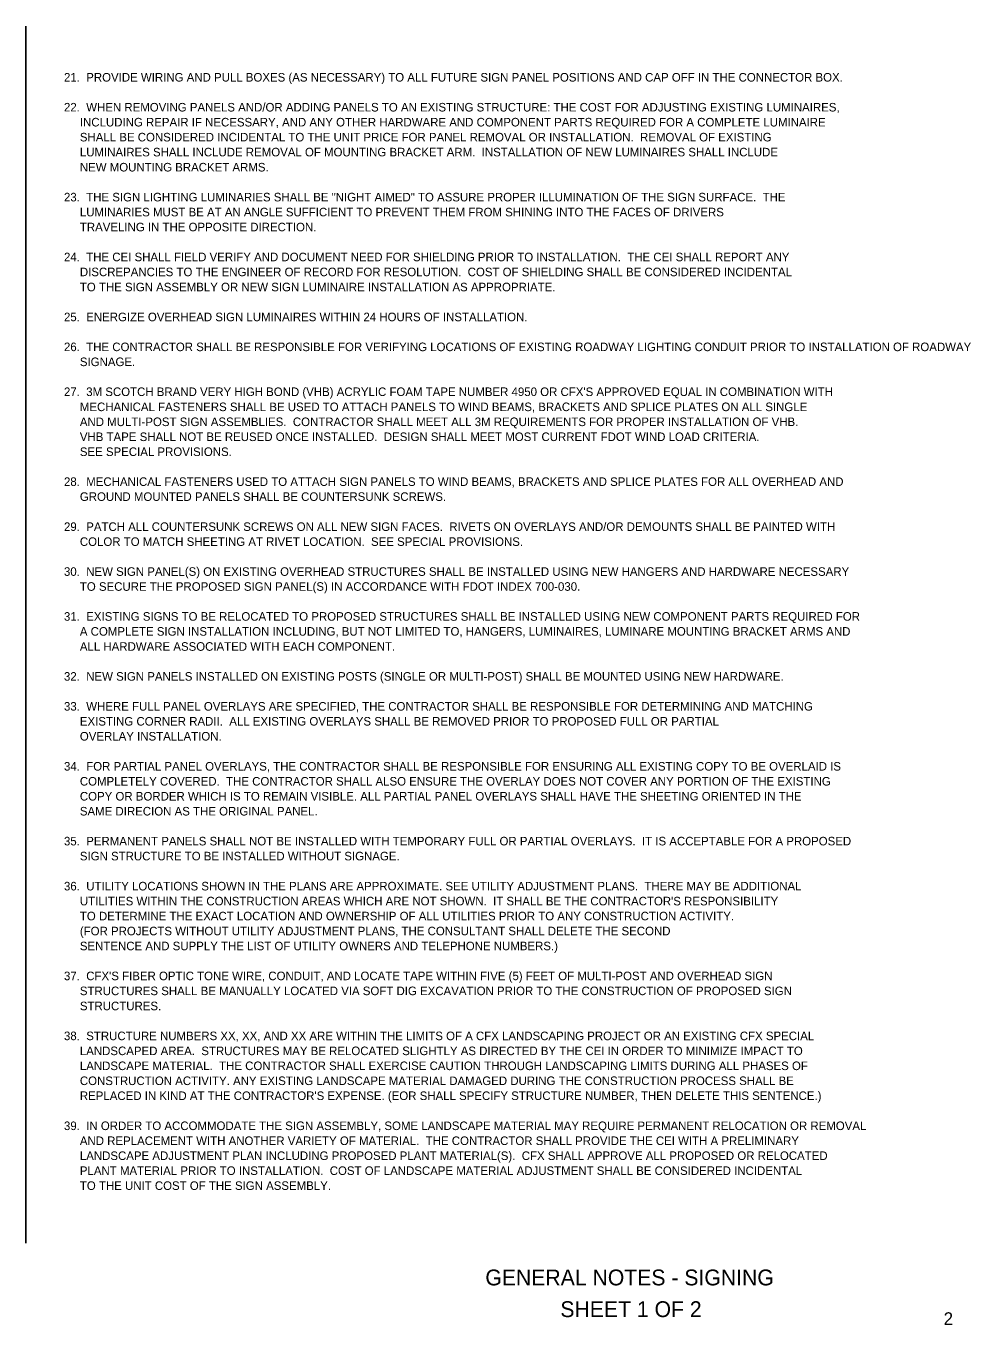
# Model space of a CAD drawing. Extents: x 2479946 to 2481516, y 3680184 to 3681234.
# Drawn here: x 2480771 to 2481516, y 3680210 to 3681234 of the extents above; entities that cross this region are included whole.
import ezdxf

# ---------------------------------------------------------------- set-up
doc = ezdxf.new("R2010")
doc.units = 0
for name, color, linetype in [('NonPlottingEle_dp', 7, 'Continuous'), ('TextLabel', 7, 'Continuous'), ('TextMisc', 7, 'Continuous'), ('TextShtNo', 7, 'Continuous')]:
    doc.layers.add(name, color=color, linetype=linetype)

msp = doc.modelspace()

# ---------------------------------------------------------------- linework, layer by layer
at = {"layer": 'NonPlottingEle_dp'}
msp.add_line((2480770.9, 3680274.2), (2480770.9, 3681234.2), dxfattribs=at)

# ---------------------------------------------------------------- texts
at = {"layer": 'TextLabel'}
for s, p in [('21.  PROVIDE WIRING AND PULL BOXES (AS NECESSARY) TO ALL FUTURE SIGN PANEL POSITIONS AND CAP OFF IN THE CONNECTOR BOX.', (2480800.9, 3681190.4)), ('22.  WHEN REMOVING PANELS AND/OR ADDING PANELS TO AN EXISTING STRUCTURE: THE COST FOR ADJUSTING EXISTING LUMINAIRES,', (2480800.9, 3681166.8)), ('     INCLUDING REPAIR IF NECESSARY, AND ANY OTHER HARDWARE AND COMPONENT PARTS REQUIRED FOR A COMPLETE LUMINAIRE', (2480800.9, 3681155)), ('     SHALL BE CONSIDERED INCIDENTAL TO THE UNIT PRICE FOR PANEL REMOVAL OR INSTALLATION.  REMOVAL OF EXISTING', (2480800.9, 3681143.2)), ('     LUMINAIRES SHALL INCLUDE REMOVAL OF MOUNTING BRACKET ARM.  INSTALLATION OF NEW LUMINAIRES SHALL INCLUDE', (2480800.9, 3681131.4)), ('     NEW MOUNTING BRACKET ARMS.', (2480800.9, 3681119.5)), ('23.  THE SIGN LIGHTING LUMINARIES SHALL BE "NIGHT AIMED" TO ASSURE PROPER ILLUMINATION OF THE SIGN SURFACE.  THE ', (2480800.9, 3681095.9)), ('     LUMINARIES MUST BE AT AN ANGLE SUFFICIENT TO PREVENT THEM FROM SHINING INTO THE FACES OF DRIVERS', (2480800.9, 3681084.1)), ('     TRAVELING IN THE OPPOSITE DIRECTION.', (2480800.9, 3681072.3)), ('24.  THE CEI SHALL FIELD VERIFY AND DOCUMENT NEED FOR SHIELDING PRIOR TO INSTALLATION.  THE CEI SHALL REPORT ANY', (2480800.9, 3681048.7)), ('     DISCREPANCIES TO THE ENGINEER OF RECORD FOR RESOLUTION.  COST OF SHIELDING SHALL BE CONSIDERED INCIDENTAL', (2480800.9, 3681036.9)), ('     TO THE SIGN ASSEMBLY OR NEW SIGN LUMINAIRE INSTALLATION AS APPROPRIATE.', (2480800.9, 3681025)), ('25.  ENERGIZE OVERHEAD SIGN LUMINAIRES WITHIN 24 HOURS OF INSTALLATION.', (2480800.9, 3681001.4)), ('26.  THE CONTRACTOR SHALL BE RESPONSIBLE FOR VERIFYING LOCATIONS OF EXISTING ROADWAY LIGHTING CONDUIT PRIOR TO INSTALLATION OF ROADWAY', (2480800.9, 3680977.8)), ('     SIGNAGE.', (2480800.9, 3680966)), ("27.  3M SCOTCH BRAND VERY HIGH BOND (VHB) ACRYLIC FOAM TAPE NUMBER 4950 OR CFX'S APPROVED EQUAL IN COMBINATION WITH", (2480800.9, 3680942.4)), ('     MECHANICAL FASTENERS SHALL BE USED TO ATTACH PANELS TO WIND BEAMS, BRACKETS AND SPLICE PLATES ON ALL SINGLE', (2480800.9, 3680930.5)), ('     AND MULTI-POST SIGN ASSEMBLIES.  CONTRACTOR SHALL MEET ALL 3M REQUIREMENTS FOR PROPER INSTALLATION OF VHB.', (2480800.9, 3680918.7)), ('     VHB TAPE SHALL NOT BE REUSED ONCE INSTALLED.  DESIGN SHALL MEET MOST CURRENT FDOT WIND LOAD CRITERIA.', (2480800.9, 3680906.9)), ('     SEE SPECIAL PROVISIONS.', (2480800.9, 3680895.1)), ('28.  MECHANICAL FASTENERS USED TO ATTACH SIGN PANELS TO WIND BEAMS, BRACKETS AND SPLICE PLATES FOR ALL OVERHEAD AND', (2480800.9, 3680871.5)), ('     GROUND MOUNTED PANELS SHALL BE COUNTERSUNK SCREWS.', (2480800.9, 3680859.7)), ('29.  PATCH ALL COUNTERSUNK SCREWS ON ALL NEW SIGN FACES.  RIVETS ON OVERLAYS AND/OR DEMOUNTS SHALL BE PAINTED WITH', (2480800.9, 3680836)), ('     COLOR TO MATCH SHEETING AT RIVET LOCATION.  SEE SPECIAL PROVISIONS.', (2480800.9, 3680824.2)), ('30.  NEW SIGN PANEL(S) ON EXISTING OVERHEAD STRUCTURES SHALL BE INSTALLED USING NEW HANGERS AND HARDWARE NECESSARY', (2480800.9, 3680800.6)), ('     TO SECURE THE PROPOSED SIGN PANEL(S) IN ACCORDANCE WITH FDOT INDEX 700-030.', (2480800.9, 3680788.8)), ('31.  EXISTING SIGNS TO BE RELOCATED TO PROPOSED STRUCTURES SHALL BE INSTALLED USING NEW COMPONENT PARTS REQUIRED FOR', (2480800.9, 3680765.2)), ('     A COMPLETE SIGN INSTALLATION INCLUDING, BUT NOT LIMITED TO, HANGERS, LUMINAIRES, LUMINARE MOUNTING BRACKET ARMS AND', (2480800.9, 3680753.4)), ('     ALL HARDWARE ASSOCIATED WITH EACH COMPONENT.', (2480800.9, 3680741.5)), ('32.  NEW SIGN PANELS INSTALLED ON EXISTING POSTS (SINGLE OR MULTI-POST) SHALL BE MOUNTED USING NEW HARDWARE.', (2480800.9, 3680717.9)), ('33.  WHERE FULL PANEL OVERLAYS ARE SPECIFIED, THE CONTRACTOR SHALL BE RESPONSIBLE FOR DETERMINING AND MATCHING', (2480800.9, 3680694.3)), ('     EXISTING CORNER RADII.  ALL EXISTING OVERLAYS SHALL BE REMOVED PRIOR TO PROPOSED FULL OR PARTIAL', (2480800.9, 3680682.5)), ('     OVERLAY INSTALLATION.', (2480800.9, 3680670.7)), ('34.  FOR PARTIAL PANEL OVERLAYS, THE CONTRACTOR SHALL BE RESPONSIBLE FOR ENSURING ALL EXISTING COPY TO BE OVERLAID IS', (2480800.9, 3680647)), ('     COMPLETELY COVERED.  THE CONTRACTOR SHALL ALSO ENSURE THE OVERLAY DOES NOT COVER ANY PORTION OF THE EXISTING', (2480800.9, 3680635.2)), ('     COPY OR BORDER WHICH IS TO REMAIN VISIBLE. ALL PARTIAL PANEL OVERLAYS SHALL HAVE THE SHEETING ORIENTED IN THE', (2480800.9, 3680623.4)), ('     SAME DIRECION AS THE ORIGINAL PANEL.', (2480800.9, 3680611.6)), ('35.  PERMANENT PANELS SHALL NOT BE INSTALLED WITH TEMPORARY FULL OR PARTIAL OVERLAYS.  IT IS ACCEPTABLE FOR A PROPOSED', (2480800.9, 3680588)), ('     SIGN STRUCTURE TO BE INSTALLED WITHOUT SIGNAGE.', (2480800.9, 3680576.2)), ('36.  UTILITY LOCATIONS SHOWN IN THE PLANS ARE APPROXIMATE. SEE UTILITY ADJUSTMENT PLANS.  THERE MAY BE ADDITIONAL', (2480800.9, 3680552.5)), ("     UTILITIES WITHIN THE CONSTRUCTION AREAS WHICH ARE NOT SHOWN.  IT SHALL BE THE CONTRACTOR'S RESPONSIBILITY", (2480800.9, 3680540.7)), ('     TO DETERMINE THE EXACT LOCATION AND OWNERSHIP OF ALL UTILITIES PRIOR TO ANY CONSTRUCTION ACTIVITY.', (2480800.9, 3680528.9)), ('     (FOR PROJECTS WITHOUT UTILITY ADJUSTMENT PLANS, THE CONSULTANT SHALL DELETE THE SECOND', (2480800.9, 3680517.1)), ('     SENTENCE AND SUPPLY THE LIST OF UTILITY OWNERS AND TELEPHONE NUMBERS.)', (2480800.9, 3680505.3)), ("37.  CFX'S FIBER OPTIC TONE WIRE, CONDUIT, AND LOCATE TAPE WITHIN FIVE (5) FEET OF MULTI-POST AND OVERHEAD SIGN", (2480800.9, 3680481.7)), ('     STRUCTURES SHALL BE MANUALLY LOCATED VIA SOFT DIG EXCAVATION PRIOR TO THE CONSTRUCTION OF PROPOSED SIGN', (2480800.9, 3680469.9)), ('     STRUCTURES.', (2480800.9, 3680458)), ('38.  STRUCTURE NUMBERS XX, XX, AND XX ARE WITHIN THE LIMITS OF A CFX LANDSCAPING PROJECT OR AN EXISTING CFX SPECIAL', (2480800.9, 3680434.4)), ('     LANDSCAPED AREA.  STRUCTURES MAY BE RELOCATED SLIGHTLY AS DIRECTED BY THE CEI IN ORDER TO MINIMIZE IMPACT TO', (2480800.9, 3680422.6)), ('     LANDSCAPE MATERIAL.  THE CONTRACTOR SHALL EXERCISE CAUTION THROUGH LANDSCAPING LIMITS DURING ALL PHASES OF', (2480800.9, 3680410.8)), ('     CONSTRUCTION ACTIVITY. ANY EXISTING LANDSCAPE MATERIAL DAMAGED DURING THE CONSTRUCTION PROCESS SHALL BE', (2480800.9, 3680399)), ("     REPLACED IN KIND AT THE CONTRACTOR'S EXPENSE. (EOR SHALL SPECIFY STRUCTURE NUMBER, THEN DELETE THIS SENTENCE.)", (2480800.9, 3680387.2)), ('39.  IN ORDER TO ACCOMMODATE THE SIGN ASSEMBLY, SOME LANDSCAPE MATERIAL MAY REQUIRE PERMANENT RELOCATION OR REMOVAL', (2480800.9, 3680363.5)), ('     AND REPLACEMENT WITH ANOTHER VARIETY OF MATERIAL.  THE CONTRACTOR SHALL PROVIDE THE CEI WITH A PRELIMINARY', (2480800.9, 3680351.7)), ('     LANDSCAPE ADJUSTMENT PLAN INCLUDING PROPOSED PLANT MATERIAL(S).  CFX SHALL APPROVE ALL PROPOSED OR RELOCATED', (2480800.9, 3680339.9)), ('     PLANT MATERIAL PRIOR TO INSTALLATION.  COST OF LANDSCAPE MATERIAL ADJUSTMENT SHALL BE CONSIDERED INCIDENTAL', (2480800.9, 3680328.1)), ('     TO THE UNIT COST OF THE SIGN ASSEMBLY.', (2480800.9, 3680316.3))]:
    msp.add_text(s, height=6.75, dxfattribs=at).set_placement(p)
at = {"layer": 'TextMisc'}
for s, p in [('GENERAL NOTES - SIGNING ', (2481133.3, 3680241)), ('      SHEET 1 OF 2      ', (2481164.6, 3680216))]:
    msp.add_text(s, height=12.5, rotation=360, dxfattribs=at).set_placement(p)
at = {"layer": 'TextShtNo'}
msp.add_text('  2  ', height=10, rotation=360, dxfattribs=at).set_placement((2481487.4, 3680209.8))

doc.saveas('drawing.dxf')
